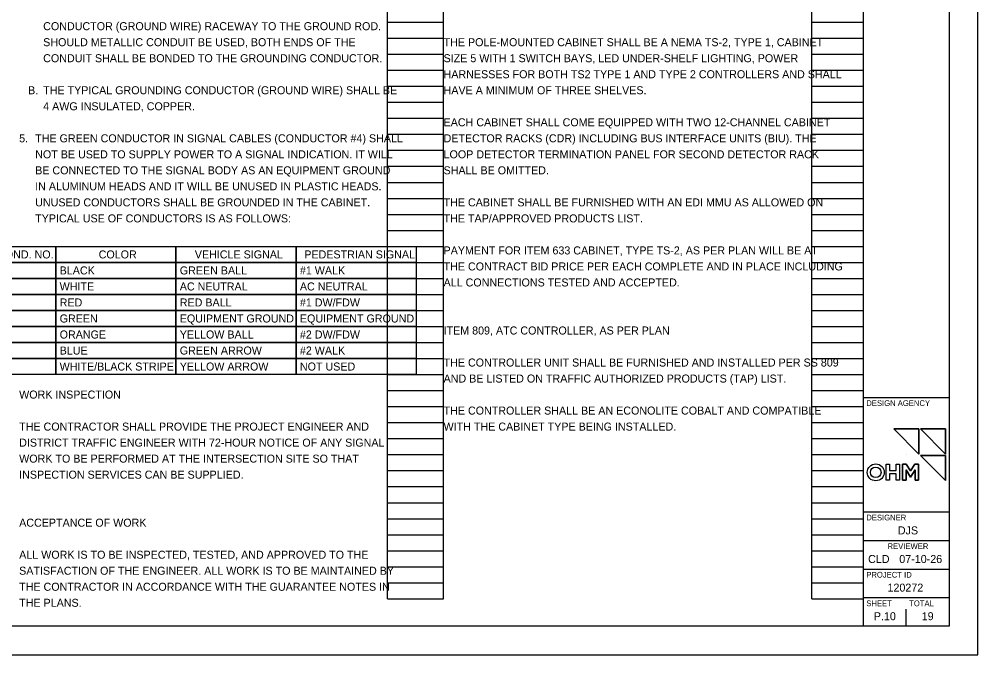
# Model space of a CAD drawing. Extents: x 0 to 34, y 0 to 22.
# Drawn here: x 17.24 to 34, y 0 to 11.11 of the extents above; entities that cross this region are included whole.
import ezdxf

# ---------------------------------------------------------------- set-up
doc = ezdxf.new("R2010")
doc.units = 0
for name, color, linetype in [('Default', 7, 'Continuous'), ('SH_Border', 7, 'Continuous'), ('SH_Cut_Line', 7, 'Continuous'), ('SH_Data', 7, 'Continuous'), ('SH_Text', 7, 'Continuous'), ('TX_P_Misc', 7, 'Continuous')]:
    doc.layers.add(name, color=color, linetype=linetype)

msp = doc.modelspace()

# ---------------------------------------------------------------- linework, layer by layer
at = {"layer": 'Default'}
for points in [[(32.966, 3.948), (32.966, 3.51), (32.53, 3.948)], [(33.433, 3.948), (33.433, 3.51), (32.997, 3.948)], [(33.433, 3.483), (33.433, 3.045), (32.997, 3.483)], [(32.397, 3.333), (32.457, 3.333), (32.457, 3.22), (32.571, 3.22), (32.571, 3.333), (32.631, 3.333), (32.631, 3.052), (32.571, 3.052), (32.571, 3.166), (32.457, 3.166), (32.457, 3.052), (32.397, 3.052)], [(32.9, 3.335), (32.963, 3.335), (32.963, 3.052), (32.903, 3.052), (32.903, 3.233), (32.824, 3.108), (32.745, 3.233), (32.745, 3.052), (32.685, 3.052), (32.685, 3.335), (32.748, 3.335), (32.824, 3.216)]]:
    msp.add_lwpolyline(points, close=True, dxfattribs=at)
at = {"layer": 'SH_Border'}
for p, q in [((32, 0.5), (32, 21.5)), ((32, 4.5), (33.5, 4.5)), ((32, 2.5), (33.5, 2.5)), ((32, 2), (33.5, 2)), ((32, 1.5), (33.5, 1.5)), ((32, 1), (33.5, 1))]:
    msp.add_line(p, q, dxfattribs=at)
msp.add_lwpolyline([(1.5, 21.5), (33.5, 21.5), (33.5, 0.5), (1.5, 0.5)], close=True, dxfattribs=at)
at = {"layer": 'SH_Cut_Line'}
msp.add_lwpolyline([(0, 0), (34, 0), (34, 22), (0, 22)], close=True, dxfattribs=at)
at = {"layer": 'SH_Data'}
for p, q in [((23.68, 0.98), (23.68, 21.14)), ((24.66, 0.98), (24.66, 21.14)), ((31.1, 0.98), (31.1, 21.14)), ((32, 0.98), (32, 21.14)), ((23.68, 11.06), (24.66, 11.06)), ((31.1, 11.06), (32, 11.06)), ((23.68, 10.78), (24.66, 10.78)), ((31.1, 10.78), (32, 10.78)), ((23.68, 10.5), (24.66, 10.5)), ((31.1, 10.5), (32, 10.5)), ((23.68, 10.22), (24.66, 10.22)), ((31.1, 10.22), (32, 10.22)), ((23.68, 9.94), (24.66, 9.94)), ((31.1, 9.94), (32, 9.94)), ((23.68, 9.66), (24.66, 9.66)), ((31.1, 9.66), (32, 9.66)), ((23.68, 9.38), (24.66, 9.38)), ((31.1, 9.38), (32, 9.38)), ((23.68, 9.1), (24.66, 9.1)), ((31.1, 9.1), (32, 9.1)), ((23.68, 8.82), (24.66, 8.82)), ((31.1, 8.82), (32, 8.82)), ((23.68, 8.54), (24.66, 8.54)), ((31.1, 8.54), (32, 8.54)), ((23.68, 8.26), (24.66, 8.26)), ((31.1, 8.26), (32, 8.26)), ((23.68, 7.98), (24.66, 7.98)), ((31.1, 7.98), (32, 7.98)), ((23.68, 7.7), (24.66, 7.7)), ((31.1, 7.7), (32, 7.7)), ((23.68, 7.42), (24.66, 7.42)), ((31.1, 7.42), (32, 7.42)), ((23.68, 7.14), (24.66, 7.14)), ((31.1, 7.14), (32, 7.14)), ((23.68, 6.86), (24.66, 6.86)), ((31.1, 6.86), (32, 6.86)), ((23.68, 6.58), (24.66, 6.58)), ((31.1, 6.58), (32, 6.58)), ((23.68, 6.3), (24.66, 6.3)), ((31.1, 6.3), (32, 6.3)), ((23.68, 6.02), (24.66, 6.02)), ((31.1, 6.02), (32, 6.02)), ((23.68, 5.74), (24.66, 5.74)), ((31.1, 5.74), (32, 5.74)), ((23.68, 5.46), (24.66, 5.46)), ((31.1, 5.46), (32, 5.46)), ((23.68, 5.18), (24.66, 5.18)), ((31.1, 5.18), (32, 5.18)), ((23.68, 4.9), (24.66, 4.9)), ((31.1, 4.9), (32, 4.9)), ((23.68, 4.62), (24.66, 4.62)), ((31.1, 4.62), (32, 4.62)), ((23.68, 4.34), (24.66, 4.34)), ((31.1, 4.34), (32, 4.34)), ((23.68, 4.06), (24.66, 4.06)), ((31.1, 4.06), (32, 4.06)), ((23.68, 3.78), (24.66, 3.78)), ((31.1, 3.78), (32, 3.78)), ((23.68, 3.5), (24.66, 3.5)), ((31.1, 3.5), (32, 3.5)), ((32.75, 3.5), (32.75, 3.5)), ((23.68, 3.22), (24.66, 3.22)), ((31.1, 3.22), (32, 3.22)), ((23.68, 2.94), (24.66, 2.94)), ((31.1, 2.94), (32, 2.94)), ((23.68, 2.66), (24.66, 2.66)), ((31.1, 2.66), (32, 2.66)), ((23.68, 2.38), (24.66, 2.38)), ((31.1, 2.38), (32, 2.38)), ((23.68, 2.1), (24.66, 2.1)), ((31.1, 2.1), (32, 2.1)), ((23.68, 1.82), (24.66, 1.82)), ((31.1, 1.82), (32, 1.82)), ((23.68, 1.54), (24.66, 1.54)), ((31.1, 1.54), (32, 1.54)), ((23.68, 1.26), (24.66, 1.26)), ((31.1, 1.26), (32, 1.26)), ((23.68, 0.98), (24.66, 0.98)), ((31.1, 0.98), (32, 0.98)), ((32.375, 0.675), (32.375, 0.675)), ((32.75, 0.5), (32.75, 0.8))]:
    msp.add_line(p, q, dxfattribs=at)
at = {"layer": 'SH_Text'}
for points in [[(16.787, 7.14), (17.881, 7.14), (17.881, 6.86), (16.787, 6.86)], [(17.881, 7.14), (19.981, 7.14), (19.981, 6.86), (17.881, 6.86)], [(19.981, 7.14), (22.081, 7.14), (22.081, 6.86), (19.981, 6.86)], [(22.081, 7.14), (24.181, 7.14), (24.181, 6.86), (22.081, 6.86)], [(16.787, 6.86), (17.881, 6.86), (17.881, 6.58), (16.787, 6.58)], [(17.881, 6.86), (19.981, 6.86), (19.981, 6.58), (17.881, 6.58)], [(19.981, 6.86), (22.081, 6.86), (22.081, 6.58), (19.981, 6.58)], [(22.081, 6.86), (24.181, 6.86), (24.181, 6.58), (22.081, 6.58)], [(16.787, 6.58), (17.881, 6.58), (17.881, 6.3), (16.787, 6.3)], [(17.881, 6.58), (19.981, 6.58), (19.981, 6.3), (17.881, 6.3)], [(19.981, 6.58), (22.081, 6.58), (22.081, 6.3), (19.981, 6.3)], [(22.081, 6.58), (24.181, 6.58), (24.181, 6.3), (22.081, 6.3)], [(16.787, 6.3), (17.881, 6.3), (17.881, 6.02), (16.787, 6.02)], [(17.881, 6.3), (19.981, 6.3), (19.981, 6.02), (17.881, 6.02)], [(19.981, 6.3), (22.081, 6.3), (22.081, 6.02), (19.981, 6.02)], [(22.081, 6.3), (24.181, 6.3), (24.181, 6.02), (22.081, 6.02)], [(16.787, 6.02), (17.881, 6.02), (17.881, 5.74), (16.787, 5.74)], [(17.881, 6.02), (19.981, 6.02), (19.981, 5.74), (17.881, 5.74)], [(19.981, 6.02), (22.081, 6.02), (22.081, 5.74), (19.981, 5.74)], [(22.081, 6.02), (24.181, 6.02), (24.181, 5.74), (22.081, 5.74)], [(16.787, 5.74), (17.881, 5.74), (17.881, 5.46), (16.787, 5.46)], [(17.881, 5.74), (19.981, 5.74), (19.981, 5.46), (17.881, 5.46)], [(19.981, 5.74), (22.081, 5.74), (22.081, 5.46), (19.981, 5.46)], [(22.081, 5.74), (24.181, 5.74), (24.181, 5.46), (22.081, 5.46)], [(16.787, 5.46), (17.881, 5.46), (17.881, 5.18), (16.787, 5.18)], [(17.881, 5.46), (19.981, 5.46), (19.981, 5.18), (17.881, 5.18)], [(19.981, 5.46), (22.081, 5.46), (22.081, 5.18), (19.981, 5.18)], [(22.081, 5.46), (24.181, 5.46), (24.181, 5.18), (22.081, 5.18)], [(16.787, 5.18), (17.881, 5.18), (17.881, 4.9), (16.787, 4.9)], [(17.881, 5.18), (19.981, 5.18), (19.981, 4.9), (17.881, 4.9)], [(19.981, 5.18), (22.081, 5.18), (22.081, 4.9), (19.981, 4.9)], [(22.081, 5.18), (24.181, 5.18), (24.181, 4.9), (22.081, 4.9)]]:
    msp.add_lwpolyline(points, close=True, dxfattribs=at)
at = {"layer": 'TX_P_Misc'}
for p, q in [((32.745, 3.052), (32.745, 3.233)), ((32.745, 3.233), (32.824, 3.108)), ((32.824, 3.108), (32.903, 3.233)), ((32.903, 3.233), (32.903, 3.052))]:
    msp.add_line(p, q, dxfattribs=at)
for points in [[(32.53, 3.948), (32.966, 3.51), (32.966, 3.948), (32.53, 3.948)], [(32.997, 3.948), (33.433, 3.51), (33.433, 3.948), (32.997, 3.948)], [(32.997, 3.483), (33.433, 3.045), (33.433, 3.483), (32.997, 3.483)], [(32.824, 3.216), (32.748, 3.335), (32.685, 3.335), (32.685, 3.052), (32.745, 3.052)], [(32.903, 3.052), (32.963, 3.052), (32.963, 3.335), (32.9, 3.335), (32.824, 3.216)]]:
    msp.add_lwpolyline(points, dxfattribs=at)
msp.add_lwpolyline([(32.397, 3.333), (32.457, 3.333), (32.457, 3.22), (32.571, 3.22), (32.571, 3.333), (32.631, 3.333), (32.631, 3.052), (32.571, 3.052), (32.571, 3.166), (32.457, 3.166), (32.457, 3.052), (32.397, 3.052)], close=True, dxfattribs=at)
for radius in [0.148, 0.148, 0.0927, 0.0927]:
    msp.add_circle((32.215, 3.19), radius, dxfattribs=at)

# ---------------------------------------------------------------- texts
at = {"layer": 'SH_Data'}
for s, height, p in [('DESIGN AGENCY', 0.1, (32.05, 4.35)), ('DESIGNER', 0.1, (32.05, 2.35)), ('DJS', 0.14, (32.602, 2.105)), ('REVIEWER', 0.1, (32.422, 1.85)), ('CLD', 0.14, (32.082, 1.605)), ('07-10-26', 0.14, (32.627, 1.605)), ('PROJECT ID', 0.1, (32.05, 1.35)), ('120272', 0.14, (32.421, 1.105)), ('SHEET', 0.1, (32.05, 0.85)), ('TOTAL', 0.1, (32.8, 0.85)), ('P.10', 0.14, (32.182, 0.605)), ('19', 0.14, (33.019, 0.605))]:
    msp.add_text(s, height=height, dxfattribs=at).set_placement(p)
at = {"layer": 'SH_Text'}
for s, p in [('CONDUCTOR (GROUND WIRE) RACEWAY TO THE GROUND ROD. ', (17.66, 10.92)), ('SHOULD METALLIC CONDUIT BE USED, BOTH ENDS OF THE ', (17.66, 10.64)), ('THE POLE-MOUNTED CABINET SHALL BE A NEMA TS-2, TYPE 1, CABINET ', (24.66, 10.64)), ('CONDUIT SHALL BE BONDED TO THE GROUNDING CONDUCTOR.', (17.66, 10.36)), ('SIZE 5 WITH 1 SWITCH BAYS, LED UNDER-SHELF LIGHTING, POWER ', (24.66, 10.36)), ('HARNESSES FOR BOTH TS2 TYPE 1 AND TYPE 2 CONTROLLERS AND SHALL ', (24.66, 10.08)), ('   B.', (17.24, 9.8)), ('THE TYPICAL GROUNDING CONDUCTOR (GROUND WIRE) SHALL BE ', (17.66, 9.8)), ('HAVE A MINIMUM OF THREE SHELVES. ', (24.66, 9.8)), ('4 AWG INSULATED, COPPER.', (17.66, 9.52)), ('EACH CABINET SHALL COME EQUIPPED WITH TWO 12-CHANNEL CABINET ', (24.66, 9.24)), ('5.', (17.24, 8.96)), ('THE GREEN CONDUCTOR IN SIGNAL CABLES (CONDUCTOR #4) SHALL ', (17.52, 8.96)), ('DETECTOR RACKS (CDR) INCLUDING BUS INTERFACE UNITS (BIU). THE ', (24.66, 8.96)), ('NOT BE USED TO SUPPLY POWER TO A SIGNAL INDICATION. IT WILL ', (17.52, 8.68)), ('LOOP DETECTOR TERMINATION PANEL FOR SECOND DETECTOR RACK ', (24.66, 8.68)), ('BE CONNECTED TO THE SIGNAL BODY AS AN EQUIPMENT GROUND ', (17.52, 8.4)), ('SHALL BE OMITTED. ', (24.66, 8.4)), ('IN ALUMINUM HEADS AND IT WILL BE UNUSED IN PLASTIC HEADS. ', (17.52, 8.12)), ('UNUSED CONDUCTORS SHALL BE GROUNDED IN THE CABINET. ', (17.52, 7.84)), ('THE CABINET SHALL BE FURNISHED WITH AN EDI MMU AS ALLOWED ON ', (24.66, 7.84)), ('TYPICAL USE OF CONDUCTORS IS AS FOLLOWS:', (17.52, 7.56)), ('THE TAP/APPROVED PRODUCTS LIST. ', (24.66, 7.56)), ('COND. NO.', (16.854, 6.93)), ('COLOR', (18.63, 6.93)), ('VEHICLE SIGNAL', (20.311, 6.93)), ('PEDESTRIAN SIGNAL', (22.225, 6.93)), ('PAYMENT FOR ITEM 633 CABINET, TYPE TS-2, AS PER PLAN WILL BE AT ', (24.66, 7)), ('BLACK', (17.948, 6.65)), ('GREEN BALL', (20.048, 6.65)), ('#1 WALK', (22.148, 6.65)), ('THE CONTRACT BID PRICE PER EACH COMPLETE AND IN PLACE INCLUDING ', (24.66, 6.72)), ('ALL CONNECTIONS TESTED AND ACCEPTED.', (24.66, 6.44)), ('WHITE', (17.948, 6.37)), ('AC NEUTRAL', (20.048, 6.37)), ('AC NEUTRAL', (22.148, 6.37)), ('RED', (17.948, 6.09)), ('RED BALL', (20.048, 6.09)), ('#1 DW/FDW', (22.148, 6.09)), ('GREEN', (17.948, 5.81)), ('EQUIPMENT GROUND', (20.048, 5.81)), ('EQUIPMENT GROUND', (22.148, 5.81)), ('ITEM 809, ATC CONTROLLER, AS PER PLAN', (24.66, 5.6)), ('ORANGE', (17.948, 5.53)), ('YELLOW BALL', (20.048, 5.53)), ('#2 DW/FDW', (22.148, 5.53)), ('BLUE', (17.948, 5.25)), ('GREEN ARROW', (20.048, 5.25)), ('#2 WALK', (22.148, 5.25)), ('WHITE/BLACK STRIPE', (17.948, 4.97)), ('YELLOW ARROW', (20.048, 4.97)), ('NOT USED', (22.148, 4.97)), ('THE CONTROLLER UNIT SHALL BE FURNISHED AND INSTALLED PER SS 809 ', (24.66, 5.04)), ('AND BE LISTED ON TRAFFIC AUTHORIZED PRODUCTS (TAP) LIST.', (24.66, 4.76)), ('WORK INSPECTION', (17.24, 4.48)), ('THE CONTROLLER SHALL BE AN ECONOLITE COBALT AND COMPATIBLE ', (24.66, 4.2)), ('THE CONTRACTOR SHALL PROVIDE THE PROJECT ENGINEER AND ', (17.24, 3.92)), ('WITH THE CABINET TYPE BEING INSTALLED.', (24.66, 3.92)), ('DISTRICT TRAFFIC ENGINEER WITH 72-HOUR NOTICE OF ANY SIGNAL ', (17.24, 3.64)), ('WORK TO BE PERFORMED AT THE INTERSECTION SITE SO THAT ', (17.24, 3.36)), ('INSPECTION SERVICES CAN BE SUPPLIED.', (17.24, 3.08)), ('ACCEPTANCE OF WORK', (17.24, 2.24)), ('ALL WORK IS TO BE INSPECTED, TESTED, AND APPROVED TO THE ', (17.24, 1.68)), ('SATISFACTION OF THE ENGINEER. ALL WORK IS TO BE MAINTAINED BY ', (17.24, 1.4)), ('THE CONTRACTOR IN ACCORDANCE WITH THE GUARANTEE NOTES IN ', (17.24, 1.12)), ('THE PLANS.', (17.24, 0.84))]:
    msp.add_text(s, height=0.14, dxfattribs=at).set_placement(p)

doc.saveas('drawing.dxf')
